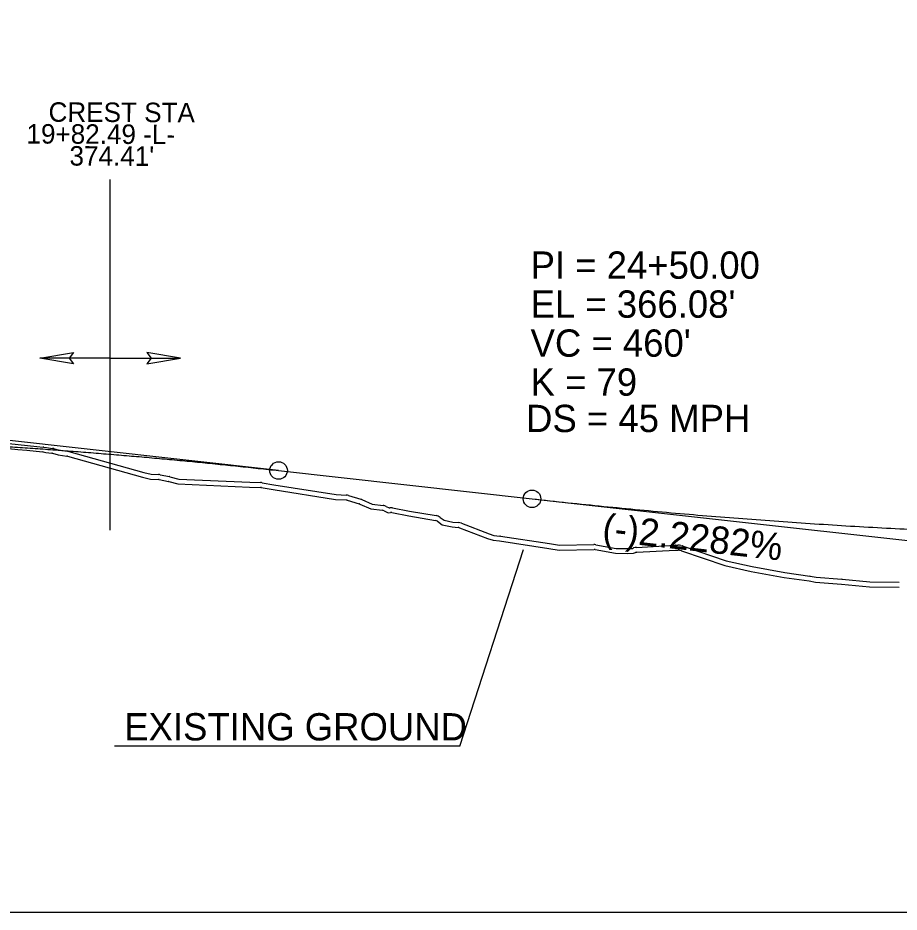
# Model space of a CAD drawing. Extents: x 1625686 to 1640492, y 1161393 to 1175642.
# Drawn here: x 1636999.9 to 1637225.9, y 1174910.8 to 1175140.2 of the extents above; entities that cross this region are included whole.
import ezdxf

# ---------------------------------------------------------------- set-up
doc = ezdxf.new("R2010")
doc.units = 0
for name, color, linetype in [('Exist Profile Cell', 7, 'Continuous'), ('Prop Plan Preparation Crest', 7, 'Continuous'), ('Prop Vertical Profile Curve Label', 7, 'Continuous'), ('Prop Vertical Profile Grade', 7, 'Continuous'), ('Prop Vertical Profile Grade Label', 7, 'Continuous'), ('Prop VPI Label', 7, 'Continuous'), ('Scratch_Level_1', 7, 'Continuous'), ('Scratch_Level_3', 7, 'Continuous')]:
    doc.layers.add(name, color=color, linetype=linetype)

msp = doc.modelspace()

# ---------------------------------------------------------------- linework, layer by layer
at = {"layer": 'Exist Profile Cell'}
msp.add_line((1635911.78, 1174910.79), (1640378.1, 1174910.79), dxfattribs=at)
at = {"layer": 'Prop Plan Preparation Crest'}
for p, q in [((1637023.6, 1175008.79), (1637023.6, 1175098.74)), ((1637023.6, 1175052.88), (1637005.6, 1175052.88)), ((1637023.6, 1175052.88), (1637041.6, 1175052.88))]:
    msp.add_line(p, q, dxfattribs=at)
for points in [[(1637014.17, 1175051.45), (1637005.6, 1175052.88), (1637014.17, 1175054.31), (1637013.1, 1175052.88)], [(1637033.04, 1175051.45), (1637041.6, 1175052.88), (1637033.04, 1175054.31), (1637034.1, 1175052.88)]]:
    msp.add_lwpolyline(points, close=True, dxfattribs=at)
at = {"layer": 'Prop Vertical Profile Curve Label'}
for centre in [(1637066.78, 1175024.05), (1637131.78, 1175016.81)]:
    msp.add_circle(centre, 2.25, dxfattribs=at)
at = {"layer": 'Prop Vertical Profile Grade'}
msp.add_line((1637066.78, 1175024.05), (1637131.78, 1175016.81), dxfattribs=at)
for points in [[(1636806.78, 1175030.62), (1636811.98, 1175030.93), (1636817.18, 1175031.22), (1636822.38, 1175031.49), (1636827.58, 1175031.75), (1636832.78, 1175031.98), (1636837.98, 1175032.2), (1636843.18, 1175032.4), (1636848.38, 1175032.58), (1636853.58, 1175032.75), (1636858.78, 1175032.89), (1636863.98, 1175033.02), (1636869.18, 1175033.13), (1636874.38, 1175033.22), (1636879.58, 1175033.3), (1636884.78, 1175033.36), (1636889.98, 1175033.39), (1636895.18, 1175033.42), (1636900.38, 1175033.42), (1636905.58, 1175033.4), (1636910.78, 1175033.37), (1636915.98, 1175033.32), (1636921.18, 1175033.25), (1636926.38, 1175033.16), (1636931.58, 1175033.06), (1636936.78, 1175032.94), (1636941.98, 1175032.8), (1636947.18, 1175032.64), (1636952.38, 1175032.46), (1636957.58, 1175032.27), (1636962.78, 1175032.06), (1636967.98, 1175031.83), (1636973.18, 1175031.58), (1636978.38, 1175031.31), (1636983.58, 1175031.03), (1636988.78, 1175030.73), (1636993.98, 1175030.41), (1636999.18, 1175030.07), (1637004.38, 1175029.72), (1637009.58, 1175029.34), (1637014.78, 1175028.95), (1637019.98, 1175028.54), (1637025.18, 1175028.11), (1637030.38, 1175027.67), (1637035.58, 1175027.21), (1637040.78, 1175026.73), (1637045.98, 1175026.23), (1637051.18, 1175025.71), (1637056.38, 1175025.18), (1637061.58, 1175024.62), (1637066.78, 1175024.05)], [(1637131.78, 1175016.81), (1637140.98, 1175015.81), (1637150.18, 1175014.87), (1637159.38, 1175013.98), (1637168.58, 1175013.14), (1637177.78, 1175012.36), (1637186.98, 1175011.63), (1637196.18, 1175010.95), (1637205.38, 1175010.33), (1637214.58, 1175009.76), (1637223.78, 1175009.25), (1637232.98, 1175008.78), (1637242.18, 1175008.38), (1637251.38, 1175008.02), (1637260.58, 1175007.72), (1637269.78, 1175007.47), (1637278.98, 1175007.28), (1637288.18, 1175007.14), (1637297.38, 1175007.06), (1637306.58, 1175007.02), (1637315.78, 1175007.05), (1637324.98, 1175007.12), (1637334.18, 1175007.25), (1637343.38, 1175007.43), (1637352.58, 1175007.67), (1637361.78, 1175007.96), (1637370.98, 1175008.3), (1637380.18, 1175008.7), (1637389.38, 1175009.15), (1637398.58, 1175009.66), (1637407.78, 1175010.21), (1637416.98, 1175010.83), (1637426.18, 1175011.49), (1637435.38, 1175012.21), (1637444.58, 1175012.99), (1637453.78, 1175013.81), (1637462.98, 1175014.69), (1637472.18, 1175015.63), (1637481.38, 1175016.61), (1637490.58, 1175017.66), (1637499.78, 1175018.75), (1637508.98, 1175019.9), (1637518.18, 1175021.1), (1637527.38, 1175022.36), (1637536.58, 1175023.67), (1637545.78, 1175025.03), (1637554.98, 1175026.45), (1637564.18, 1175027.92), (1637573.38, 1175029.44), (1637582.58, 1175031.02), (1637591.78, 1175032.65)]]:
    msp.add_spline(points, degree=3, dxfattribs=at)
at = {"layer": 'Prop VPI Label'}
for p, q in [((1637066.78, 1175024.05), (1636939.52, 1175038.23)), ((1637131.78, 1175016.81), (1637359.05, 1174991.49)), ((1637113.29, 1174953.37), (1637129.56, 1175003.8)), ((1637113.29, 1174953.37), (1637024.68, 1174953.37))]:
    msp.add_line(p, q, dxfattribs=at)
at = {"layer": 'Scratch_Level_1'}
for p, q in [((1637036.41, 1175022.98), (1637038.77, 1175022.51)), ((1637036.17, 1175021.75), (1637038.53, 1175021.28)), ((1637084.39, 1175016.46), (1637087.48, 1175015.52)), ((1637084.75, 1175017.65), (1637087.84, 1175016.72)), ((1637123.65, 1175007.23), (1637136.22, 1175005.31)), ((1637123.46, 1175006), (1637136.04, 1175004.07)), ((1637158.59, 1175004.35), (1637168.52, 1175004.89)), ((1637168.54, 1175004.89), (1637169.17, 1175004.91)), ((1637169.93, 1175004.83), (1637170.34, 1175004.72)), ((1637158.65, 1175003.1), (1637168.58, 1175003.64)), ((1637168.6, 1175003.64), (1637169.23, 1175003.67)), ((1637169.6, 1175003.63), (1637170.01, 1175003.52))]:
    msp.add_line(p, q, dxfattribs=at)
for points in [[(1636991.68, 1175032.95), (1636993.7, 1175032.01), (1636995.25, 1175031.29), (1636995.39, 1175031.27), (1636996.86, 1175031.05), (1636997.65, 1175030.97), (1637000.02, 1175030.72), (1637002.4, 1175030.48), (1637004.77, 1175030.24), (1637006.45, 1175030.07)], [(1636991.15, 1175031.82), (1636993.17, 1175030.88), (1636994.88, 1175030.08), (1636995.2, 1175030.03), (1636996.7, 1175029.81), (1636997.52, 1175029.72), (1636999.9, 1175029.48), (1637002.27, 1175029.24), (1637004.65, 1175029), (1637006.33, 1175028.83)], [(1637006.56, 1175030.06), (1637007.26, 1175029.96), (1637008.8, 1175029.74)], [(1637006.38, 1175028.82), (1637007.08, 1175028.72), (1637008.62, 1175028.5)], [(1637008.78, 1175028.47), (1637010.23, 1175028.06), (1637012.48, 1175027.76)], [(1637009.11, 1175029.67), (1637010.48, 1175029.29), (1637012.64, 1175029)], [(1637012.66, 1175027.73), (1637031.92, 1175022.32), (1637033.98, 1175021.85), (1637035.97, 1175021.77)], [(1637013, 1175028.93), (1637032.23, 1175023.53), (1637034.15, 1175023.09), (1637036.02, 1175023.02)], [(1637038.61, 1175021.26), (1637040.98, 1175020.63), (1637059.33, 1175019.79), (1637062.16, 1175019.73)], [(1637038.93, 1175022.47), (1637041.17, 1175021.87), (1637059.37, 1175021.04), (1637062.19, 1175020.98)], [(1637062.58, 1175020.94), (1637065.57, 1175020.4), (1637081.55, 1175017.88), (1637084.14, 1175017.76)], [(1637062.36, 1175019.71), (1637065.36, 1175019.17), (1637081.42, 1175016.63), (1637084.08, 1175016.51)], [(1637088.14, 1175016.6), (1637090.79, 1175015.41), (1637093.56, 1175015.11)], [(1637087.63, 1175015.46), (1637090.46, 1175014.19), (1637093.43, 1175013.86)], [(1637093.84, 1175013.74), (1637094.92, 1175013.21), (1637095.44, 1175013.27)], [(1637094.39, 1175014.86), (1637095.14, 1175014.49), (1637095.32, 1175014.51)], [(1637096.03, 1175014.48), (1637100.37, 1175013.66), (1637107.21, 1175012.49)], [(1637095.8, 1175013.25), (1637100.14, 1175012.43), (1637107, 1175011.26)], [(1637108.24, 1175012.05), (1637109.26, 1175011.33), (1637111.49, 1175010.82), (1637112.93, 1175010.71)], [(1637107.51, 1175011.04), (1637108.73, 1175010.16), (1637111.31, 1175009.58), (1637112.84, 1175009.46)], [(1637113.2, 1175009.38), (1637120.34, 1175006.61), (1637121.77, 1175006.17), (1637123.39, 1175006.01)], [(1637113.65, 1175010.55), (1637120.75, 1175007.79), (1637122.02, 1175007.4), (1637123.52, 1175007.25)], [(1637136.24, 1175005.31), (1637138.81, 1175004.9), (1637147.65, 1175005.07)], [(1637148.16, 1175005.03), (1637153.31, 1175004.08), (1637156.25, 1175004.04), (1637157.53, 1175004.07), (1637157.83, 1175004.19)], [(1637170.51, 1175004.67), (1637181.59, 1175000.87), (1637188.23, 1174999.42), (1637196.62, 1174997.9), (1637203, 1174996.97)], [(1637136.04, 1175004.07), (1637138.72, 1175003.65), (1637147.68, 1175003.82)], [(1637147.93, 1175003.8), (1637153.19, 1175002.83), (1637156.25, 1175002.79), (1637157.77, 1175002.83), (1637158.28, 1175003.02)], [(1637170.1, 1175003.49), (1637181.25, 1174999.66), (1637187.98, 1174998.19), (1637196.42, 1174996.66), (1637202.82, 1174995.73)], [(1637202.86, 1174995.73), (1637204.5, 1174995.43), (1637211.13, 1174994.94)], [(1637203.09, 1174996.96), (1637204.66, 1174996.67), (1637211.22, 1174996.19)], [(1637211.28, 1174996.18), (1637218.35, 1174995.5), (1637225.91, 1174995.4)], [(1637211.16, 1174994.94), (1637218.29, 1174994.25), (1637225.9, 1174994.15)]]:
    msp.add_lwpolyline(points, dxfattribs=at)
for centre, radius, start, end in [((1637006.2, 1175027.59), 2.5, 81.7015, 84.3102), ((1637008.44, 1175027.26), 2.5, 74.3581, 81.7276), ((1637006.2, 1175027.59), 1.25, 81.7015, 84.3102), ((1637008.44, 1175027.26), 1.25, 74.3581, 81.7276), ((1637012.32, 1175026.52), 1.25, 74.3274, 82.5472), ((1637012.32, 1175026.52), 2.5, 74.3274, 82.5472), ((1637035.93, 1175020.53), 2.5, 78.7875, 87.8569), ((1637035.93, 1175020.53), 1.25, 78.7875, 87.8569), ((1637038.29, 1175020.06), 1.25, 75.0468, 78.7875), ((1637038.29, 1175020.06), 2.5, 75.0468, 78.7875), ((1637062.14, 1175018.48), 2.5, 79.7937, 88.886), ((1637062.14, 1175018.48), 1.25, 79.7937, 88.886), ((1637084.02, 1175015.26), 1.25, 73.1382, 87.3004), ((1637084.02, 1175015.26), 2.5, 73.1382, 87.3004), ((1637087.12, 1175014.32), 2.5, 65.8078, 73.1382), ((1637087.12, 1175014.32), 1.25, 65.8078, 73.1382), ((1637093.29, 1175012.62), 1.25, 63.8825, 83.6701), ((1637093.29, 1175012.62), 2.5, 63.8825, 83.6701), ((1637095.57, 1175012.02), 2.5, 79.3272, 95.7764), ((1637095.57, 1175012.02), 1.25, 79.3272, 95.7764), ((1637106.78, 1175010.02), 2.5, 54.3124, 80.243), ((1637106.78, 1175010.02), 1.25, 54.3124, 80.243), ((1637112.74, 1175008.22), 1.25, 68.7688, 85.7534), ((1637112.74, 1175008.22), 2.5, 68.7688, 85.7534), ((1637123.27, 1175004.76), 2.5, 81.2886, 84.2381), ((1637123.27, 1175004.76), 1.25, 81.2886, 84.2381), ((1637135.85, 1175002.84), 2.5, 80.9888, 81.2886), ((1637147.7, 1175002.57), 2.5, 79.5001, 91.1428), ((1637168.65, 1175002.39), 2.5, 92.5471, 93.1046), ((1637169.28, 1175002.42), 2.5, 75.0945, 92.5471), ((1637169.69, 1175002.31), 2.5, 71.049, 75.0945), ((1637135.85, 1175002.84), 1.25, 80.9888, 81.2886), ((1637147.7, 1175002.57), 1.25, 79.5001, 91.1428), ((1637158.72, 1175001.85), 2.5, 93.1046, 110.8091), ((1637158.72, 1175001.85), 1.25, 93.1046, 110.8091), ((1637168.65, 1175002.39), 1.25, 92.5471, 93.1046), ((1637169.28, 1175002.42), 1.25, 75.0945, 92.5471), ((1637169.69, 1175002.31), 1.25, 71.049, 75.0945), ((1637202.64, 1174994.5), 1.25, 79.6536, 81.7203), ((1637202.64, 1174994.5), 2.5, 79.6536, 81.7203), ((1637211.03, 1174993.69), 2.5, 84.4712, 85.8109), ((1637211.03, 1174993.69), 1.25, 84.4712, 85.8109)]:
    msp.add_arc(centre, radius, start, end, dxfattribs=at)
at = {"layer": 'Scratch_Level_3'}
msp.add_lwpolyline([(1635911.78, 1174910.79), (1640049.19, 1174910.79), (1640049.19, 1175362.47)], dxfattribs=at)

# ---------------------------------------------------------------- texts
at = {"layer": 'Prop Plan Preparation Crest'}
for s, p in [('CREST STA', (1637007.79, 1175113.52)), ('19+82.49 -L-', (1637002.13, 1175107.94)), ("374.41'", (1637013.16, 1175102.28))]:
    msp.add_text(s, height=5, rotation=359.7547, dxfattribs=at).set_placement(p)
at = {"layer": 'Prop Vertical Profile Curve Label'}
for s, p in [("VC = 460'", (1637131.4, 1175053.25)), ('K = 79', (1637131.4, 1175043.25)), ('DS = 45 MPH', (1637130.25, 1175033.92))]:
    msp.add_text(s, height=7, dxfattribs=at).set_placement(p)
at = {"layer": 'Prop Vertical Profile Grade Label'}
msp.add_text('(-)2.2282%', height=7, rotation=353.6428, dxfattribs=at).set_placement((1637149.58, 1175006.06))
at = {"layer": 'Prop VPI Label'}
for s, p in [('PI = 24+50.00', (1637131.4, 1175073.25)), ("EL = 366.08'", (1637131.4, 1175063.25)), ('EXISTING GROUND', (1637027.2, 1174954.82))]:
    msp.add_text(s, height=7, dxfattribs=at).set_placement(p)

doc.saveas('drawing.dxf')
